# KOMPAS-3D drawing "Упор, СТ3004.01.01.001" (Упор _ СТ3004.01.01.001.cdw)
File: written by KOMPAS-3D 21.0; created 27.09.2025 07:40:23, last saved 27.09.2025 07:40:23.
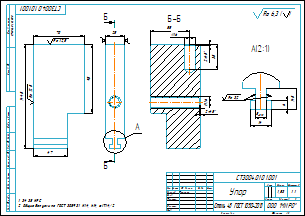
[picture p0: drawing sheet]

Sheet 1: A3, landscape

Document properties: Полное имя файла: C:\Users\Lutik\Yandex.Disk\Документы\Новая папка\Стапель №2\Стапель _ СТ3004.00.00.000\Опора _ СТ3004.01.00.000\2D\Кронштейн _ СТ3004.01.01.000\Упор _ СТ3004.01.01.001.cdw; Знак неуказанной шероховатости: 4; Параметр неуказанной шероховатости: Ra 6,3; Масса: 1.534235

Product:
- Part/product: Упор  | designation СТ3004.01.01.001
    Материал: Сталь 45  ГОСТ 1050-2013 (density 7810 kg/m3)
    Масса: 1.534235

Title block, sheet 1: Наименование: Упор; designation: СТ3004.01.01.001; Материал: Сталь 45  ГОСТ 1050-2013; Масса: 1,53; Количество листов документа: 1; organisation: ООО "МИРО"; Форматы листов документа: A3; Разработал: Тимонин

Views: Вид 1, Спереди, Проекционный вид 2, Разрез А-А, Выносной элемент 4, Выносной элемент А, Выносной элемент
Referenced files in C:\Users\Lutik\Yandex.Disk\Документы\Новая папка\Стапель №2\Стапель _ СТ3004.00.00.000\Опора _ СТ3004.01.00.000\3D\Кронштейн _ СТ3004.01.01.000\: Упор _ СТ3004.01.01.001.m3d
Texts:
  Ra 12,5
  Ra 3,2
  Ra 6,3
  Ra 6,3 ( )
  СТ3004.01.01.000
  СТ3004.01.01.001 Упор
Dimensions and other numbers on the sheet: 144,5; 70; 95; 47; 25; 55; 16; 2; 35; 14,5; 6; 8; 14; 1:1; 1; 1,53

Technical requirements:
  34...38 HRC.
  Общие допуски по ГОСТ 30893.1: Н14, h14, ± IT14/2.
